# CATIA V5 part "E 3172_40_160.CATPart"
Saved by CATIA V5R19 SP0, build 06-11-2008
Nomenclature: E 3172_40_160
Description: PART-E 3172_40_160-DESC
Material "Brass": density 8216 kg/m3, Young's modulus 1.31e+11 Pa, Poisson ratio 0.35, thermal expansion 1.67e-05 1/K
Bounding box of the stored display mesh (mm): x 0 to 160, y -20 to 20, z 0 to 6
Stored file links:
  G:\UTB\Kombinované\Bakalářská práce\Catia\FORMA\E 3172_40_160.CATPart
  D:\Aplikace\CATIA\Nová složka\win_b64\startup\materials\Catalog.CATMaterial
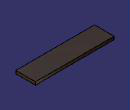
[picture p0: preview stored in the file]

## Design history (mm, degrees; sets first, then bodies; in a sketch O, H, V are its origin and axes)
Body1 "E 3172_40_160" (main body)
  Solid1: solid without history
